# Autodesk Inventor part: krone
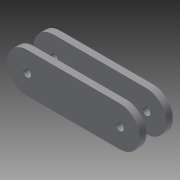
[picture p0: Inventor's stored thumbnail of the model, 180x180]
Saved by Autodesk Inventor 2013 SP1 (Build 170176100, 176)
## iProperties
Created: 2012-11
Part Number: krone
Material: Allgemein
Document SubType Name: Modeling
Designer: macuser
Density: 1 g/cm^3
Author: macuser
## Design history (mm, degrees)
sketch "Skizze1"
  geometry: L1 (140, 0)-(-140, 0) reference; L2 (0, -42)-(0, 42) reference; L3 (-70, 30)-(70, 30); L4 (70, 30)-(70, -30); L5 (70, -30)-(-70, -30); L6 (-70, -30)-(-70, 30); C1 r 30 at (-70, 0); 2 further points
  constraints: 8 end point, 2 midpoint, 2 parallel, 1 centre point, 1 horizontal, 1 perpendicular, 1 tangent, 1 vertical alignment, 4 other
  dimensions: "d0" = 140 distance of L4.end L5.end; "d1" = 60 distance of L3.end L4.end
extrude "Extrusion3" join sketch "Skizze1" distance "d43" = 50; taper "d44" = 0 deg
feature "Wandstärke2" dims "d45" = 10
sketch "Skizze4"
  geometry: C1 r 6 at (-70, 0); C2 r 6 at (70, 0); A1 r 30 centre (-70, 0) between (-70, 30) and (-70, -30) reference; A2 r 30 centre (70, 0) between (70, -30) and (70, 30) reference; 1 further point
  constraints: 2 centre point, 2 coincident
  dimensions: "d46" = 12 diameter of C1; "d47" = 12 diameter of C2
extrude "Extrusion4" cut sketch "Skizze4" distance "d48" = 50; taper "d49" = 0 deg
sketch "Skizze5"
  geometry: C1 r 6 at (0, 30) reference; C2 r 6 at (140, 30) reference; C3 r 35 at (0, 30); C4 r 35 at (140, 30); A1 r 30 centre (140, 30) between (140, 0) and (140, 60) reference; A2 r 30 centre (0, 30) between (0, 60) and (0, 0) reference; 1 further point
  constraints: 2 centre point, 2 coincident
  dimensions: "d50" = 70 diameter of C3; "d51" = 70 diameter of C4
extrude "Extrusion5" cut sketch "Skizze5" distance "d52" = 30; taper "d53" = 0 deg
sketch "Skizze6"
  geometry: L1 (70, -10)-(70, 60) reference; L2 (210, 0)-(-70, 0) reference; L3 (70, 0)-(70, 25); C1 r 6 at (70, 25)
  constraints: 2 end point, 1 centre point, 1 coincident, 1 midpoint
  dimensions: "d54" = 25 distance of L3.start L3.end; "d56" = 12 diameter of C1
extrude "Extrusion6" cut sketch "Skizze6" distance "d57" = 10; taper "d58" = 0 deg
feature "Gewinde1" dims "d59" = 10, "d60" = 0
node "Volumenkörper1"
